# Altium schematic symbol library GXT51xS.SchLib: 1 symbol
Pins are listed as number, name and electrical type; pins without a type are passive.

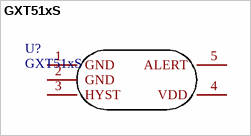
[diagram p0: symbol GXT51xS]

## GXT51xS
designator U?
footprint SOT-23-5
pins: 1 GND, 2 GND, 3 HYST, 4 VDD, 5 ALERT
